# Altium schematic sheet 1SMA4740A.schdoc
size 127 x 101 mm
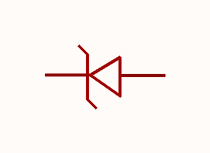
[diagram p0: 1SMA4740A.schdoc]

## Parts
D?  1sma4740a_c173486  [SMA_L4.4-W2.6-LS5.0-RD]  (value not drawn)

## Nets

Not connected (* = marked no-connect by the designer): D? 1(K) 2(A)

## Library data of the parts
D? = 1sma4740a_c173486: 二极管配置:1个独立式;稳压值(标称值):10V;稳压值(范围):9.5V~10.5V;耗散功率(Pd):1W;; Manufacturer: MDD(辰达半导体); AddInBom: yes; ModelId: a2d22152f8d5421c8e96dbd56af7c345; ModelTransform: 204.724,98.425,0,0,0,0,0,0,0; Diode Configuration: 1个独立式; Zener Voltage(Nom): 10V; Reverse Leakage Current (Ir): 10uA@7V; Pd - Power Dissipation: 1W; Impedance(Zzt): 7Ω; Operating Junction Temperature Range: -55℃~+150℃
